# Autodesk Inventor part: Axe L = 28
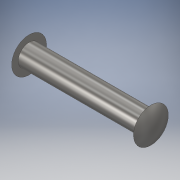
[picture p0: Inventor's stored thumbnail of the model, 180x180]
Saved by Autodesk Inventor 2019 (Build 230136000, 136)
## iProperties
Created: 2018-06
Part Number: Axe L = 28
Material: Acier inoxydable
Document SubType Name: Modeling
Designer: Fabian Perrée
Density: 8 g/cm^3
Appearance: Semi-poli
Author: Fabian Perrée
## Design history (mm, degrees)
sketch "Esquisse1"
  geometry: L1 (-14, 0)-(14, 0); L2 (14, 2.5)-(-14, 2.5); L3 (14, 2.5)-(14, 4); L4 (14, 0)-(15.072, 0); L5 (0, 2.5)-(0, 0); L6 (-14, 2.5)-(-14, 4); L7 (-15.072, 0)-(-14, 0); A1 r 8 centre (7.072, 0) between (15.072, 0) and (14, 4); A2 r 8 centre (-7.072, 0) between (-14, 4) and (-15.072, 0); 1 further point
  constraints: 14 end point, 4 horizontal, 4 point on circle, 3 symmetric about line, 2 centre point, 2 midpoint, 2 point on line, 1 coincident, 1 perpendicular, 1 vertical, 1 other
  dimensions: "d0" = 28 distance of L1.start L1.end; "d1" = 5 diameter of L2 L1; "d2" = 8 diameter of L3.end L1; "d3" = 16 diameter of A1
revolve "Révolution1" sketch "Esquisse1" stored, may be unused: angle "d4" = 90 deg
node "Solide1"
